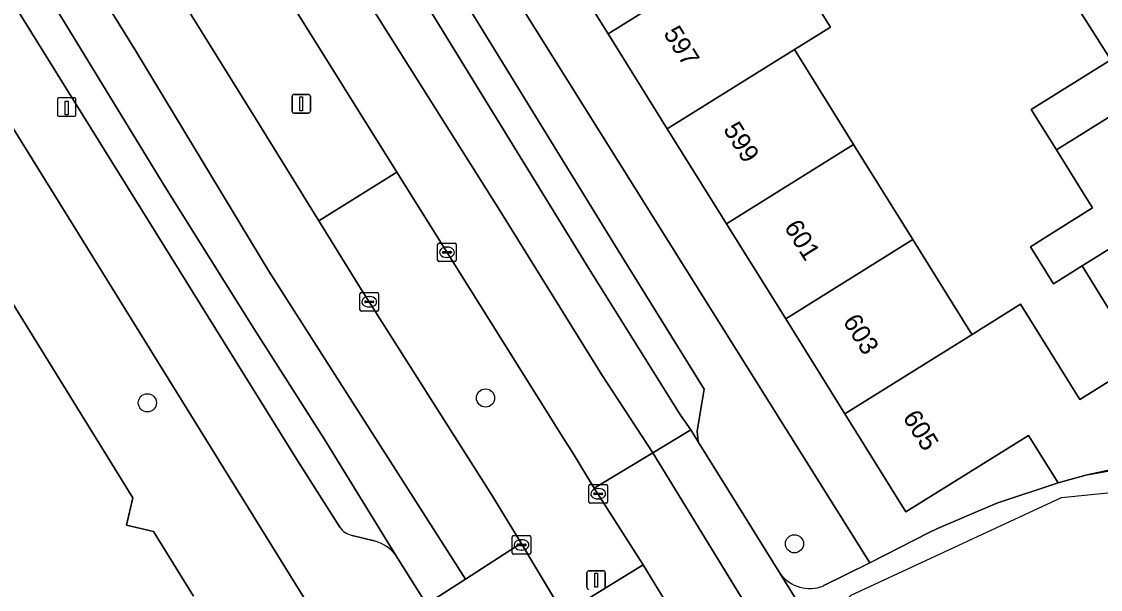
# Model space of a CAD drawing. Extents: x 157767 to 159172, y 387839 to 389425.
# Drawn here: x 158720.1 to 158778.2, y 388070.6 to 388101.2 of the extents above; entities that cross this region are included whole.
import ezdxf

# ---------------------------------------------------------------- set-up
doc = ezdxf.new("R2010")
doc.units = 0
for name, color, linetype in [('IMGEO_Berm_groen', 7, 'Continuous'), ('IMGEO_Boom', 7, 'Continuous'), ('IMGEO_Erf', 7, 'Continuous'), ('IMGEO_Fietspad_open', 7, 'Continuous'), ('IMGEO_Kolk', 7, 'Continuous'), ('IMGEO_Laadpaal', 7, 'Continuous'), ('IMGEO_Lichtmast', 7, 'Continuous'), ('IMGEO_Pand', 7, 'Continuous'), ('IMGEO_Pand_nummerreeks', 7, 'Continuous'), ('IMGEO_Parkeervlak_open', 7, 'Continuous'), ('IMGEO_Rijbaan_lokaal_gesloten', 7, 'Continuous'), ('IMGEO_Rijbaan_lokaal_open', 7, 'Continuous'), ('IMGEO_Voetpad_open', 7, 'Continuous')]:
    doc.layers.add(name, color=color, linetype=linetype)

msp = doc.modelspace()

# ---------------------------------------------------------------- linework, layer by layer
at = {"layer": 'IMGEO_Berm_groen'}
for points in [[(158731.411, 388107.326), (158725.178, 388117.248), (158721.077, 388114.643), (158726.373, 388106.161), (158732.656, 388096.033), (158736.089, 388090.495), (158740.295, 388093.103)], [(158740.295, 388093.103), (158736.089, 388090.495), (158738.301, 388086.925), (158745.451, 388075.668), (158746.985, 388073.135), (158747.767, 388071.845), (158749.269, 388069.332), (158753.558, 388071.961), (158750.922, 388076.09), (158749.797, 388077.971), (158749.242, 388078.803)]]:
    msp.add_lwpolyline(points, close=True, dxfattribs=at)
at = {"layer": 'IMGEO_Boom'}
for centre in [(158726.849, 388080.693), (158745.068, 388080.952), (158761.711, 388073.102)]:
    msp.add_circle(centre, 0.489, dxfattribs=at)
at = {"layer": 'IMGEO_Erf'}
for points in [[(158743.064, 388137.832), (158746.254, 388132.715), (158743.612, 388131.068), (158746.802, 388125.951), (158749.992, 388120.834), (158753.182, 388115.717), (158756.372, 388110.6), (158756.45, 388110.474), (158757.609, 388111.196), (158759.201, 388108.642), (158757, 388107.269), (158758.519, 388104.833), (158760.456, 388106.04), (158763.646, 388100.923), (158761.709, 388099.716), (158764.899, 388094.598), (158768.089, 388089.482), (158771.161, 388084.554), (158771.279, 388084.364), (158773.895, 388085.995), (158777.094, 388080.863), (158779.945, 388082.64)], [(158725.193, 388136.821), (158765.78, 388072.075), (158768.969, 388073.702), (158769.41, 388073.92), (158772.607, 388075.298), (158775.913, 388076.385), (158774.32, 388078.939), (158767.717, 388074.822), (158764.43, 388080.095), (158761.24, 388085.212), (158758.05, 388090.329), (158754.86, 388095.446), (158751.67, 388100.564), (158748.48, 388105.68), (158749.516, 388106.326), (158749.416, 388106.487), (158746.326, 388111.443), (158743.136, 388116.561), (158739.946, 388121.678), (158736.756, 388126.794), (158733.566, 388131.912), (158730.278, 388137.186)], [(158778.837, 388085.449), (158777.209, 388088.062), (158775.672, 388087.104), (158774.428, 388089.099), (158775.942, 388090.044), (158777.775, 388091.188), (158777.329, 388091.904), (158775.83, 388094.307), (158774.473, 388096.484), (158778.759, 388099.156), (158775.217, 388104.739)], [(158737.779, 388053.263), (158742.17, 388056.603), (158742.727, 388058.158), (158738.82, 388064.497), (158716.081, 388101.143), (158691.111, 388085.534), (158661.715, 388067.158), (158686.368, 388027.385), (158687.799, 388025.086)], [(158674.573, 388066.522), (158688.823, 388075.351), (158688.23, 388076.308), (158688.603, 388077.895), (158710.859, 388091.683), (158712.127, 388089.636), (158713.424, 388089.332), (158714.806, 388089.007), (158716.926, 388090.32), (158726.064, 388075.57), (158725.721, 388074.11), (158727.181, 388073.767), (158729.34, 388070.281)], [(158782.882, 388077.983), (158777.402, 388076.8), (158780.952, 388077.441)]]:
    msp.add_lwpolyline(points, dxfattribs=at)
at = {"layer": 'IMGEO_Fietspad_open'}
for points in [[(158812.157, 388075.952), (158812.197, 388076.541), (158804.72, 388077.107), (158794.726, 388077.87), (158790.079, 388078.115), (158786.42, 388078.016), (158783.083, 388077.665), (158780.952, 388077.441), (158777.402, 388076.8), (158775.913, 388076.385), (158772.607, 388075.298), (158769.41, 388073.92), (158768.969, 388073.702), (158765.78, 388072.075), (158763.264, 388070.83)], [(158760.955, 388071.476), (158762.89, 388068.369), (158762.89, 388068.369), (158764.763, 388070.328), (158776.102, 388075.6), (158794.916, 388077.498), (158812.157, 388075.952)]]:
    msp.add_lwpolyline(points, dxfattribs=at)
msp.add_arc((158762.54, 388072.692), 1.998, 217.48988, 291.24956, dxfattribs=at)
at = {"layer": 'IMGEO_Kolk'}
for p, q in [((158742.488, 388088.37), (158742.488, 388089.222)), ((158742.563, 388089.296), (158743.415, 388089.296)), ((158743.489, 388089.222), (158743.489, 388088.37)), ((158742.747, 388088.79), (158742.747, 388088.802)), ((158743.185, 388088.753), (158742.787, 388088.753)), ((158742.79, 388088.839), (158743.188, 388088.839)), ((158742.976, 388089.076), (158743.001, 388089.076)), ((158743.231, 388088.802), (158743.231, 388088.79)), ((158743.415, 388088.296), (158742.563, 388088.296)), ((158742.999, 388088.516), (158742.974, 388088.516)), ((158738.3, 388085.705), (158738.3, 388086.557)), ((158738.375, 388086.631), (158739.227, 388086.631)), ((158738.788, 388086.411), (158738.813, 388086.411)), ((158739.301, 388086.557), (158739.301, 388085.705)), ((158738.559, 388086.125), (158738.559, 388086.137)), ((158738.997, 388086.088), (158738.599, 388086.088)), ((158738.602, 388086.174), (158739, 388086.174)), ((158738.811, 388085.851), (158738.786, 388085.851)), ((158739.043, 388086.137), (158739.043, 388086.125)), ((158739.227, 388085.631), (158738.375, 388085.631)), ((158750.637, 388075.368), (158750.637, 388076.22)), ((158750.712, 388076.294), (158751.564, 388076.294)), ((158750.896, 388075.788), (158750.896, 388075.8)), ((158750.939, 388075.837), (158751.337, 388075.837)), ((158751.125, 388076.074), (158751.15, 388076.074)), ((158751.38, 388075.8), (158751.38, 388075.788)), ((158751.638, 388076.22), (158751.638, 388075.368)), ((158751.564, 388075.294), (158750.712, 388075.294)), ((158751.334, 388075.751), (158750.936, 388075.751)), ((158751.148, 388075.514), (158751.123, 388075.514)), ((158746.507, 388072.615), (158746.507, 388073.467)), ((158746.582, 388073.541), (158747.434, 388073.541)), ((158747.508, 388073.467), (158747.508, 388072.615)), ((158746.766, 388073.035), (158746.766, 388073.047)), ((158747.204, 388072.998), (158746.806, 388072.998)), ((158746.809, 388073.084), (158747.207, 388073.084)), ((158746.995, 388073.321), (158747.02, 388073.321)), ((158747.25, 388073.047), (158747.25, 388073.035)), ((158747.434, 388072.541), (158746.582, 388072.541)), ((158747.018, 388072.761), (158746.993, 388072.761))]:
    msp.add_line(p, q, dxfattribs=at)
for points in [[(158742.488, 388088.37), (158742.488, 388089.222)], [(158742.563, 388089.296), (158743.415, 388089.296)], [(158743.489, 388089.222), (158743.489, 388088.37)], [(158743.415, 388088.296), (158742.563, 388088.296)], [(158738.3, 388085.705), (158738.3, 388086.557)], [(158738.375, 388086.631), (158739.227, 388086.631)], [(158739.301, 388086.557), (158739.301, 388085.705)], [(158739.227, 388085.631), (158738.375, 388085.631)], [(158750.637, 388075.368), (158750.637, 388076.22)], [(158750.712, 388076.294), (158751.564, 388076.294)], [(158751.638, 388076.22), (158751.638, 388075.368)], [(158751.564, 388075.294), (158750.712, 388075.294)], [(158746.507, 388072.615), (158746.507, 388073.467)], [(158746.582, 388073.541), (158747.434, 388073.541)], [(158747.508, 388073.467), (158747.508, 388072.615)], [(158747.434, 388072.541), (158746.582, 388072.541)]]:
    msp.add_lwpolyline(points, dxfattribs=at)
for centre, radius, start, end in [((158742.565, 388089.22), 0.0765, 91.55205, 178.44795), ((158742.565, 388089.22), 0.0765, 91.55205, 178.44795), ((158743.413, 388089.22), 0.0765, 1.55205, 88.44795), ((158743.413, 388089.22), 0.0765, 1.55205, 88.44795), ((158742.787, 388088.799), 0.0403, 85.87752, 175.75265), ((158742.784, 388088.789), 0.0366, 178.93798, 274.71019), ((158743.188, 388088.796), 0.043, 264.86636, 352.45326), ((158743.192, 388088.801), 0.0386, 1.73085, 96.63898), ((158742.565, 388088.372), 0.0765, 181.55205, 268.44795), ((158742.565, 388088.372), 0.0765, 181.55205, 268.44795), ((158743.413, 388088.372), 0.0765, 271.55205, 358.44795), ((158743.413, 388088.372), 0.0765, 271.55205, 358.44795), ((158738.377, 388086.555), 0.0765, 91.55205, 178.44795), ((158738.377, 388086.555), 0.0765, 91.55205, 178.44795), ((158739.225, 388086.555), 0.0765, 1.55205, 88.44795), ((158739.225, 388086.555), 0.0765, 1.55205, 88.44795), ((158738.377, 388085.707), 0.0765, 181.55205, 268.44795), ((158738.377, 388085.707), 0.0765, 181.55205, 268.44795), ((158738.599, 388086.134), 0.0403, 85.87752, 175.75265), ((158738.596, 388086.124), 0.0366, 178.93798, 274.71019), ((158739, 388086.131), 0.043, 264.86636, 352.45326), ((158739.004, 388086.136), 0.0386, 1.73085, 96.63898), ((158739.225, 388085.707), 0.0765, 271.55205, 358.44795), ((158739.225, 388085.707), 0.0765, 271.55205, 358.44795), ((158750.714, 388076.218), 0.0765, 91.55205, 178.44795), ((158750.714, 388076.218), 0.0765, 91.55205, 178.44795), ((158750.936, 388075.797), 0.0403, 85.87752, 175.75265), ((158750.933, 388075.787), 0.0366, 178.93798, 274.71019), ((158751.337, 388075.794), 0.043, 264.86636, 352.45326), ((158751.341, 388075.799), 0.0386, 1.73085, 96.63898), ((158751.562, 388076.218), 0.0765, 1.55205, 88.44795), ((158751.562, 388076.218), 0.0765, 1.55205, 88.44795), ((158750.714, 388075.37), 0.0765, 181.55205, 268.44795), ((158750.714, 388075.37), 0.0765, 181.55205, 268.44795), ((158751.562, 388075.37), 0.0765, 271.55205, 358.44795), ((158751.562, 388075.37), 0.0765, 271.55205, 358.44795), ((158746.584, 388073.465), 0.0765, 91.55205, 178.44795), ((158746.584, 388073.465), 0.0765, 91.55205, 178.44795), ((158747.432, 388073.465), 0.0765, 1.55205, 88.44795), ((158747.432, 388073.465), 0.0765, 1.55205, 88.44795), ((158746.806, 388073.044), 0.0403, 85.87752, 175.75265), ((158746.803, 388073.034), 0.0366, 178.93798, 274.71019), ((158747.207, 388073.041), 0.043, 264.86636, 352.45326), ((158747.211, 388073.046), 0.0386, 1.73085, 96.63898), ((158746.584, 388072.617), 0.0765, 181.55205, 268.44795), ((158746.584, 388072.617), 0.0765, 181.55205, 268.44795), ((158747.432, 388072.617), 0.0765, 271.55205, 358.44795), ((158747.432, 388072.617), 0.0765, 271.55205, 358.44795)]:
    msp.add_arc(centre, radius, start, end, dxfattribs=at)
for centre, major_axis, ratio, start_param, end_param in [((158742.975, 388088.796), (-0.387, 0.002), 0.722429, 4.712389, 7.853982), ((158743, 388088.796), (-0.39, 0.002), 0.717154, 1.570796, 4.712389), ((158738.787, 388086.131), (-0.387, 0.002), 0.722429, 4.712389, 7.853982), ((158738.812, 388086.131), (-0.39, 0.002), 0.717154, 1.570796, 4.712389), ((158751.124, 388075.794), (-0.387, 0.002), 0.722429, 4.712389, 7.853982), ((158751.149, 388075.794), (-0.39, 0.002), 0.717154, 1.570796, 4.712389), ((158746.994, 388073.041), (-0.387, 0.002), 0.722429, 4.712389, 7.853982), ((158747.019, 388073.041), (-0.39, 0.002), 0.717154, 1.570796, 4.712389)]:
    msp.add_ellipse(centre, major_axis=major_axis, ratio=ratio, start_param=start_param, end_param=end_param, dxfattribs=at)
at = {"layer": 'IMGEO_Laadpaal'}
for p, q in [((158722.002, 388097.035), (158722.002, 388096.194)), ((158722.002, 388097.035), (158722.002, 388096.194)), ((158722.918, 388097.119), (158722.077, 388097.119)), ((158722.918, 388097.119), (158722.077, 388097.119)), ((158723.002, 388096.203), (158723.002, 388097.044)), ((158723.002, 388096.203), (158723.002, 388097.044)), ((158722.086, 388096.119), (158722.927, 388096.119)), ((158722.086, 388096.119), (158722.927, 388096.119))]:
    msp.add_line(p, q, dxfattribs=at)
msp.add_lwpolyline([(158722.417, 388096.932), (158722.577, 388096.932), (158722.577, 388096.199), (158722.417, 388096.199), (158722.417, 388096.932)], dxfattribs=at)
for centre, start, end in [((158722.08, 388097.041), 92.4484, 184.28452), ((158722.08, 388097.041), 92.4484, 184.28452), ((158722.924, 388097.041), 2.4484, 94.28452), ((158722.924, 388097.041), 2.4484, 94.28452), ((158722.08, 388096.197), 182.4484, 274.28452), ((158722.08, 388096.197), 182.4484, 274.28452), ((158722.924, 388096.197), 272.4484, 4.28452), ((158722.924, 388096.197), 272.4484, 4.28452)]:
    msp.add_arc(centre, 0.0779, start, end, dxfattribs=at)
at = {"layer": 'IMGEO_Lichtmast'}
for p, q in [((158734.742, 388097.292), (158735.532, 388097.292)), ((158735.532, 388097.292), (158734.742, 388097.292)), ((158734.642, 388096.392), (158734.642, 388097.192)), ((158734.642, 388097.192), (158734.642, 388096.392)), ((158735.632, 388097.192), (158735.632, 388096.392)), ((158735.632, 388096.392), (158735.632, 388097.192)), ((158735.532, 388096.292), (158734.742, 388096.292)), ((158734.742, 388096.292), (158735.532, 388096.292)), ((158750.532, 388070.746), (158750.532, 388071.546)), ((158750.532, 388071.546), (158750.532, 388070.746)), ((158750.632, 388071.646), (158751.422, 388071.646)), ((158751.422, 388071.646), (158750.632, 388071.646)), ((158751.522, 388071.546), (158751.522, 388070.746)), ((158751.522, 388070.746), (158751.522, 388071.546))]:
    msp.add_line(p, q, dxfattribs=at)
for points in [[(158735.062, 388097.167), (158735.212, 388097.167), (158735.212, 388096.417), (158735.062, 388096.417), (158735.062, 388097.167)], [(158750.952, 388071.521), (158751.102, 388071.521), (158751.102, 388070.771), (158750.952, 388070.771), (158750.952, 388071.521)]]:
    msp.add_lwpolyline(points, dxfattribs=at)
for centre, start, end in [((158734.742, 388097.192), 90, 180), ((158734.742, 388097.192), 90, 180), ((158735.532, 388097.192), 0, 90), ((158735.532, 388097.192), 360, 90), ((158734.742, 388096.392), 180, 270), ((158734.742, 388096.392), 180, 270), ((158735.532, 388096.392), 270, 0), ((158735.532, 388096.392), 270, 0), ((158750.632, 388071.546), 90, 180), ((158750.632, 388071.546), 90, 180), ((158751.422, 388071.546), 0, 90), ((158751.422, 388071.546), 360, 90), ((158750.632, 388070.746), 180, 270), ((158750.632, 388070.746), 180, 270), ((158751.422, 388070.746), 270, 0), ((158751.422, 388070.746), 270, 0)]:
    msp.add_arc(centre, 0.1, start, end, dxfattribs=at)
at = {"layer": 'IMGEO_Pand'}
for points in [[(158757, 388107.269), (158759.201, 388108.642), (158757.609, 388111.196), (158756.45, 388110.474), (158756.372, 388110.6), (158749.516, 388106.326), (158748.48, 388105.68), (158751.67, 388100.564), (158758.519, 388104.833)], [(158758.519, 388104.833), (158751.67, 388100.564), (158754.86, 388095.446), (158761.709, 388099.716), (158763.646, 388100.923), (158760.456, 388106.04)], [(158758.05, 388090.329), (158764.899, 388094.598), (158761.709, 388099.716), (158754.86, 388095.446)], [(158775.83, 388094.307), (158780.116, 388096.979), (158778.759, 388099.156), (158774.473, 388096.484)], [(158780.116, 388096.979), (158775.83, 388094.307), (158777.329, 388091.904), (158777.775, 388091.188), (158775.942, 388090.044), (158774.428, 388089.099), (158775.672, 388087.104), (158777.209, 388088.062), (158783.296, 388091.856)], [(158768.089, 388089.482), (158764.899, 388094.598), (158758.05, 388090.329), (158761.24, 388085.212)], [(158783.296, 388091.856), (158777.209, 388088.062), (158778.837, 388085.449), (158780.714, 388086.62), (158782.239, 388084.174), (158786.449, 388086.798)], [(158768.089, 388089.482), (158761.24, 388085.212), (158764.43, 388080.095), (158771.279, 388084.364), (158771.161, 388084.554)], [(158780.088, 388082.411), (158779.945, 388082.64), (158777.094, 388080.863), (158773.895, 388085.995), (158771.279, 388084.364), (158764.43, 388080.095), (158767.717, 388074.822), (158774.32, 388078.939), (158775.913, 388076.385), (158777.402, 388076.8), (158782.882, 388077.983)]]:
    msp.add_lwpolyline(points, close=True, dxfattribs=at)
msp.add_lwpolyline([(158729.34, 388070.281), (158727.181, 388073.767), (158725.721, 388074.11), (158726.064, 388075.57), (158716.926, 388090.32), (158714.806, 388089.007), (158713.424, 388089.332), (158712.127, 388089.636), (158710.859, 388091.683), (158688.603, 388077.895), (158688.23, 388076.308), (158688.823, 388075.351), (158674.573, 388066.522)], dxfattribs=at)
at = {"layer": 'IMGEO_Parkeervlak_open'}
for points in [[(158722.749, 388132.751), (158724.061, 388130.697), (158728.837, 388122.969), (158740.105, 388105.052), (158750.634, 388087.925), (158755.577, 388080.025), (158756.126, 388079.24), (158756.524, 388078.598), (158756.478, 388079.173), (158756.854, 388081.429), (158752.209, 388088.899), (158741.678, 388106.03), (158730.409, 388123.949), (158726.244, 388130.689)], [(158740.216, 388072.504), (158736.373, 388078.752), (158732.593, 388084.691), (158727.798, 388092.33), (158722.314, 388101.287), (158716.28, 388110.925), (158709.196, 388122.348)], [(158709.02, 388119.232), (158734.901, 388077.644), (158737.217, 388074)], [(158737.882, 388073.555), (158739.07, 388073.254)]]:
    msp.add_lwpolyline(points, dxfattribs=at)
for centre, radius, start, end in [((158738.1, 388074.6), 1.068, 214.20234, 258.21892), ((158738.578, 388071.252), 2.062, 37.39862, 76.19588)]:
    msp.add_arc(centre, radius, start, end, dxfattribs=at)
at = {"layer": 'IMGEO_Rijbaan_lokaal_gesloten'}
for points in [[(158717.852, 388129.025), (158725.178, 388117.248), (158731.411, 388107.326), (158740.295, 388093.103), (158749.242, 388078.803), (158749.797, 388077.971), (158750.922, 388076.09), (158754.085, 388078.005), (158751.334, 388082.198), (158745.833, 388091.038), (158737.528, 388104.244), (158727.681, 388119.9), (158720.109, 388131.939), (158722.336, 388133.375), (158719.936, 388136.946)], [(158708.957, 388122.733), (158709.196, 388122.348), (158716.28, 388110.925), (158722.314, 388101.287), (158727.798, 388092.33), (158732.593, 388084.691), (158736.373, 388078.752), (158740.216, 388072.504), (158741.891, 388069.848), (158743.983, 388071.197), (158740.753, 388076.253), (158733.391, 388087.775), (158726.201, 388099.653), (158712.286, 388122.072), (158708.425, 388127.273)], [(158708.425, 388127.273), (158712.286, 388122.072), (158726.201, 388099.653), (158733.391, 388087.775), (158740.753, 388076.253), (158743.983, 388071.197), (158746.985, 388073.135), (158745.451, 388075.668), (158738.301, 388086.925), (158736.089, 388090.495), (158732.656, 388096.033), (158726.373, 388106.161)], [(158761.125, 388066.522), (158754.085, 388078.005), (158750.922, 388076.09), (158753.558, 388071.961), (158755.149, 388069.378)], [(158750.868, 388066.781), (158749.269, 388069.332), (158747.767, 388071.845), (158746.985, 388073.135), (158743.983, 388071.197), (158741.891, 388069.848)]]:
    msp.add_lwpolyline(points, dxfattribs=at)
for points in [[(158740.105, 388105.052), (158728.837, 388122.969), (158724.061, 388130.697), (158722.749, 388132.751), (158722.572, 388133.024), (158722.336, 388133.375), (158720.109, 388131.939), (158727.681, 388119.9), (158737.528, 388104.244), (158745.833, 388091.038), (158751.334, 388082.198), (158754.085, 388078.005), (158756.126, 388079.24), (158755.577, 388080.025), (158750.634, 388087.925)], [(158761.125, 388066.522), (158762.89, 388068.369), (158762.89, 388068.369), (158760.955, 388071.476), (158758.15, 388075.974), (158756.524, 388078.598), (158756.126, 388079.24), (158754.085, 388078.005)]]:
    msp.add_lwpolyline(points, close=True, dxfattribs=at)
at = {"layer": 'IMGEO_Rijbaan_lokaal_open'}
msp.add_lwpolyline([(158757.228, 388136.446), (158759.02, 388133.567), (158762.208, 388128.449), (158763.648, 388126.139), (158767.174, 388120.584), (158768.633, 388118.243), (158770.047, 388115.976), (158768.76, 388115.174), (158772.379, 388109.29), (158773.692, 388107.185), (158775.217, 388104.739), (158778.759, 388099.156)], dxfattribs=at)
at = {"layer": 'IMGEO_Voetpad_open'}
for points in [[(158763.264, 388070.83), (158765.78, 388072.075), (158725.193, 388136.821)], [(158726.244, 388130.689), (158730.409, 388123.949), (158741.678, 388106.03), (158752.209, 388088.899), (158756.854, 388081.429), (158756.478, 388079.173), (158756.524, 388078.598), (158758.15, 388075.974), (158760.955, 388071.476)], [(158737.217, 388074), (158734.901, 388077.644), (158709.02, 388119.232)], [(158705.712, 388117.72), (158715.101, 388102.438), (158716.081, 388101.143), (158738.82, 388064.497), (158742.727, 388058.158), (158744.092, 388056.055)], [(158739.07, 388073.254), (158737.882, 388073.555)], [(158741.891, 388069.848), (158740.216, 388072.504)]]:
    msp.add_lwpolyline(points, dxfattribs=at)
msp.add_lwpolyline([(158750.868, 388066.781), (158755.149, 388069.378), (158753.558, 388071.961), (158749.269, 388069.332)], close=True, dxfattribs=at)
for centre, radius, start, end in [((158738.1, 388074.6), 1.068, 214.20234, 258.21892), ((158738.578, 388071.252), 2.062, 37.39862, 76.19588), ((158762.54, 388072.692), 1.998, 217.48988, 291.24956)]:
    msp.add_arc(centre, radius, start, end, dxfattribs=at)

# ---------------------------------------------------------------- texts
at = {"layer": 'IMGEO_Pand_nummerreeks'}
for s, rotation, p in [('597', 301.93909, (158754.623, 388100.588)), ('599', 301.93909, (158757.846, 388095.419)), ('601', 301.93909, (158761.129, 388090.154)), ('603', 301.93646, (158764.292, 388085.079)), ('605', 301.93646, (158767.515, 388079.909))]:
    msp.add_text(s, height=1, rotation=rotation, dxfattribs=at).set_placement(p)

doc.saveas('drawing.dxf')
